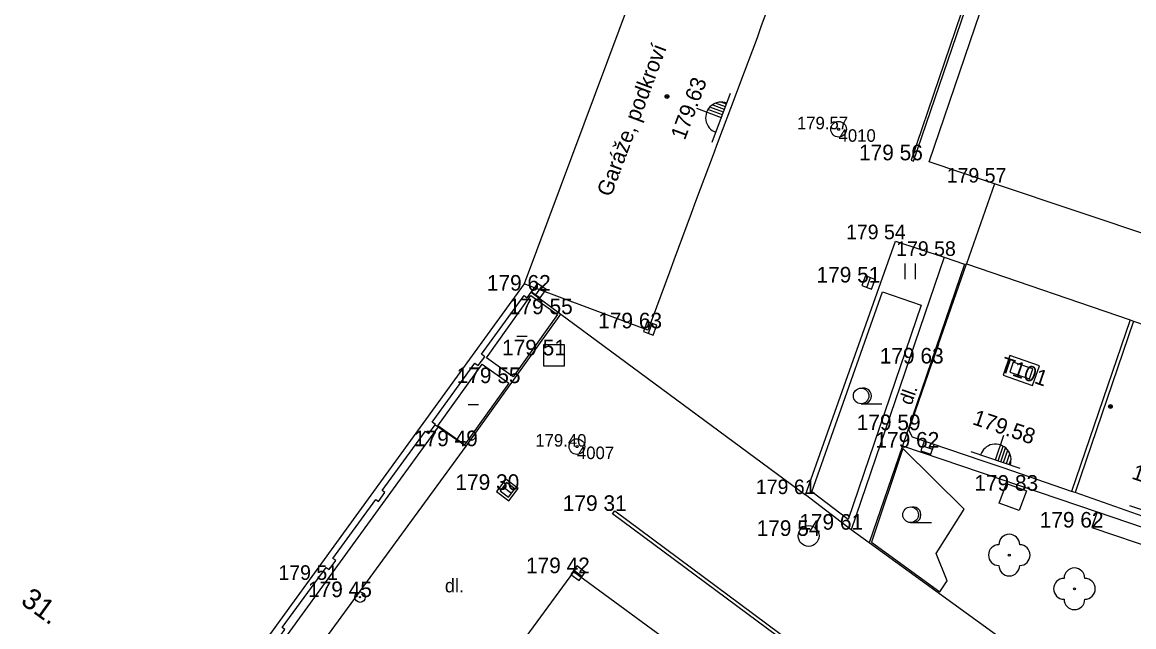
# Model space of a CAD drawing. Extents: x -537755 to -537431, y -1180722 to -1180510.
# Drawn here: x -537558.4 to -537505, y -1180613 to -1180583.9 of the extents above; entities that cross this region are included whole.
import ezdxf

# ---------------------------------------------------------------- set-up
doc = ezdxf.new("R2010")
doc.units = 0
for name, color, linetype in [('Vrstva 1', 7, 'Continuous'), ('Vrstva 10', 7, 'Continuous'), ('Vrstva 11', 7, 'Continuous'), ('Vrstva 21', 7, 'Continuous'), ('Vrstva 22', 7, 'Continuous'), ('Vrstva 23', 7, 'Continuous'), ('Vrstva 24', 7, 'Continuous'), ('Vrstva 25', 7, 'Continuous'), ('Vrstva 26', 7, 'Continuous'), ('Vrstva 27', 7, 'Continuous'), ('Vrstva 3', 7, 'Continuous'), ('Vrstva 36', 7, 'Continuous'), ('Vrstva 37', 7, 'Continuous'), ('Vrstva 39', 7, 'Continuous'), ('Vrstva 40', 7, 'Continuous'), ('Vrstva 41', 7, 'Continuous'), ('Vrstva 47', 7, 'Continuous'), ('Vrstva 5', 7, 'Continuous'), ('Vrstva 6', 7, 'Continuous'), ('Vrstva 7', 7, 'Continuous'), ('Vrstva 8', 7, 'Continuous')]:
    doc.layers.add(name, color=color, linetype=linetype)

msp = doc.modelspace()

# ---------------------------------------------------------------- linework, layer by layer
at = {"layer": 'Vrstva 1'}
for p, q in [((-537523.07, -1180584.66), (-537523.07, -1180584.66)), ((-537524.12, -1180587.47), (-537524.12, -1180587.47)), ((-537525.17, -1180590.29), (-537525.17, -1180590.29)), ((-537515.67, -1180590.55), (-537515.67, -1180590.55)), ((-537515.13, -1180590.55), (-537515.13, -1180590.55)), ((-537512.78, -1180591.38), (-537512.78, -1180591.38)), ((-537511.79, -1180591.73), (-537511.79, -1180591.73)), ((-537511.62, -1180591.62), (-537511.62, -1180591.62)), ((-537516.46, -1180594.34), (-537516.46, -1180594.34)), ((-537527.06, -1180595.35), (-537527.06, -1180595.35)), ((-537514.05, -1180595.14), (-537514.05, -1180595.14)), ((-537513.07, -1180595.43), (-537513.07, -1180595.43)), ((-537513.01, -1180595.53), (-537513.01, -1180595.53)), ((-537517.71, -1180596.42), (-537517.71, -1180596.42)), ((-537534.12, -1180597.12), (-537534.12, -1180597.12)), ((-537534.11, -1180597.15), (-537534.11, -1180597.15)), ((-537533.55, -1180596.81), (-537533.55, -1180596.81)), ((-537532.65, -1180597.96), (-537532.65, -1180597.96)), ((-537532.49, -1180597.94), (-537532.49, -1180597.94)), ((-537528.11, -1180598.17), (-537528.11, -1180598.17)), ((-537528.32, -1180598.7), (-537528.32, -1180598.7)), ((-537528.2, -1180598.62), (-537528.2, -1180598.62)), ((-537532.82, -1180599.92), (-537532.82, -1180599.92)), ((-537514.67, -1180600.31), (-537514.67, -1180600.31)), ((-537535, -1180601.25), (-537535, -1180601.25)), ((-537534.78, -1180600.95), (-537534.78, -1180600.95)), ((-537537.57, -1180602.14), (-537537.57, -1180602.14)), ((-537536.26, -1180603.2), (-537536.26, -1180603.2)), ((-537515.78, -1180603.51), (-537515.78, -1180603.51)), ((-537515.6, -1180603.84), (-537515.6, -1180603.84)), ((-537537.12, -1180604.21), (-537537.12, -1180604.21)), ((-537537.05, -1180604.28), (-537537.05, -1180604.28)), ((-537516.08, -1180604.26), (-537516.08, -1180604.26)), ((-537514.88, -1180604.35), (-537514.88, -1180604.35)), ((-537512.15, -1180605.02), (-537512.15, -1180605.02)), ((-537511.08, -1180606.07), (-537511.08, -1180606.07)), ((-537535.06, -1180606.38), (-537535.06, -1180606.38)), ((-537520.79, -1180606.58), (-537520.79, -1180606.58)), ((-537510.13, -1180606.42), (-537510.13, -1180606.42)), ((-537541.26, -1180606.94), (-537541.26, -1180606.94)), ((-537534.99, -1180606.9), (-537534.99, -1180606.9)), ((-537513.11, -1180607.3), (-537513.11, -1180607.3)), ((-537529.9, -1180607.39), (-537529.9, -1180607.39)), ((-537506.73, -1180607.43), (-537506.73, -1180607.43)), ((-537518.54, -1180608.29), (-537518.54, -1180608.29)), ((-537506.99, -1180608.19), (-537506.99, -1180608.19)), ((-537520.59, -1180608.59), (-537520.59, -1180608.59)), ((-537514.46, -1180609.44), (-537514.46, -1180609.44)), ((-537510.95, -1180609.51), (-537510.95, -1180609.51)), ((-537543.62, -1180610.2), (-537543.62, -1180610.2)), ((-537531.89, -1180610.31), (-537531.89, -1180610.31)), ((-537531.67, -1180610.38), (-537531.67, -1180610.38)), ((-537543.73, -1180610.7), (-537543.73, -1180610.7)), ((-537513.93, -1180610.74), (-537513.93, -1180610.74)), ((-537542.14, -1180611.53), (-537542.14, -1180611.53)), ((-537507.82, -1180611.13), (-537507.82, -1180611.13))]:
    msp.add_line(p, q, dxfattribs=at)
at = {"layer": 'Vrstva 10'}
for p, q in [((-537491.645, -1180598.392), (-537511.66, -1180591.68)), ((-537520.733, -1180606.623), (-537516.42, -1180594.43)), ((-537537.05, -1180604.28), (-537532.49, -1180597.94)), ((-537544.365, -1180614.287), (-537537.05, -1180604.28)), ((-537518.54, -1180608.29), (-537520.733, -1180606.623)), ((-537517.675, -1180608.917), (-537518.54, -1180608.29)), ((-537502.79, -1180619.71), (-537517.675, -1180608.917))]:
    msp.add_line(p, q, dxfattribs=at)
msp.add_lwpolyline([(-537516.42, -1180594.43), (-537514.076, -1180595.208), (-537513.104, -1180595.531), (-537513.01, -1180595.53)], dxfattribs=at)
at = {"layer": 'Vrstva 11'}
for p, q in [((-537510.498, -1180575.39), (-537515.67, -1180590.55)), ((-537515.547, -1180590.592), (-537510.376, -1180575.435)), ((-537515.67, -1180590.55), (-537515.547, -1180590.592)), ((-537514.076, -1180595.208), (-537518.54, -1180608.29)), ((-537513.104, -1180595.531), (-537516.08, -1180604.26)), ((-537533.919, -1180596.884), (-537532.49, -1180597.94)), ((-537532.49, -1180597.94), (-537520.733, -1180606.623)), ((-537538.392, -1180603.352), (-537545.644, -1180613.334)), ((-537516.08, -1180604.26), (-537517.675, -1180608.917)), ((-537516.08, -1180604.26), (-537506.73, -1180607.43)), ((-537530.007, -1180607.535), (-537529.9, -1180607.39)), ((-537515.91, -1180617.97), (-537530.007, -1180607.535)), ((-537529.9, -1180607.39), (-537515.81, -1180617.84)), ((-537506.73, -1180607.43), (-537506.99, -1180608.19)), ((-537506.73, -1180607.43), (-537499.88, -1180609.77)), ((-537506.99, -1180608.19), (-537493.67, -1180612.7))]:
    msp.add_line(p, q, dxfattribs=at)
for points in [[(-537538.525, -1180603.26), (-537538.392, -1180603.352), (-537537.05, -1180604.28)], [(-537535.58, -1180606.45), (-537534.99, -1180606.9), (-537534.54, -1180606.31), (-537535.13, -1180605.86), (-537535.58, -1180606.45)], [(-537511.08, -1180606.07), (-537510.13, -1180606.42), (-537510.48, -1180607.37), (-537511.43, -1180607.02), (-537511.08, -1180606.07)]]:
    msp.add_lwpolyline(points, dxfattribs=at)
at = {"layer": 'Vrstva 21'}
for p, q in [((-537520.434, -1180606.474), (-537517.038, -1180596.873)), ((-537517.038, -1180596.873), (-537515.176, -1180597.509)), ((-537515.176, -1180597.509), (-537518.69, -1180607.8)), ((-537518.69, -1180607.8), (-537520.434, -1180606.474)), ((-537513.93, -1180610.74), (-537514.46, -1180609.44))]:
    msp.add_line(p, q, dxfattribs=at)
for points in [[(-537516.059, -1180604.392), (-537517.563, -1180608.893), (-537514.285, -1180611.282), (-537513.93, -1180610.74)], [(-537514.46, -1180609.44), (-537513.11, -1180607.3), (-537516.059, -1180604.392)]]:
    msp.add_lwpolyline(points, dxfattribs=at)
for centre, radius in [((-537519.15, -1180589.06), 0.375), ((-537519.15, -1180589.06), 0.05), ((-537531.72, -1180604.3), 0.375), ((-537531.72, -1180604.3), 0.05)]:
    msp.add_circle(centre, radius, dxfattribs=at)
at = {"layer": 'Vrstva 22'}
for centre in [(-537510.95, -1180609.51), (-537507.82, -1180611.13)]:
    msp.add_circle(centre, 0.05, dxfattribs=at)
for centre, start, end in [((-537510.95, -1180609.01), 0, 180), ((-537511.45, -1180609.51), 90, 270), ((-537510.45, -1180609.51), 270, 90), ((-537510.95, -1180610.01), 180, 0), ((-537507.82, -1180610.63), 0, 180), ((-537508.32, -1180611.13), 90, 270), ((-537507.32, -1180611.13), 270, 90), ((-537507.82, -1180611.63), 180, 0)]:
    msp.add_arc(centre, 0.5, start, end, dxfattribs=at)
at = {"layer": 'Vrstva 24'}
for points in [[(-537509.504, -1180600.416), (-537510.923, -1180599.93), (-537511.246, -1180600.876), (-537509.827, -1180601.362)], [(-537509.821, -1180600.571), (-537510.767, -1180600.248), (-537510.929, -1180600.721), (-537509.983, -1180601.044)]]:
    msp.add_lwpolyline(points, close=True, dxfattribs=at)
at = {"layer": 'Vrstva 25'}
for radius in [0.25, 0.0303]:
    msp.add_circle((-537542.14, -1180611.53), radius, dxfattribs=at)
at = {"layer": 'Vrstva 26'}
msp.add_lwpolyline([(-537533.32, -1180600.42), (-537532.32, -1180600.42), (-537532.32, -1180599.42), (-537533.32, -1180599.42)], close=True, dxfattribs=at)
at = {"layer": 'Vrstva 27'}
for p, q in [((-537533.695, -1180597.014), (-537533.405, -1180596.606)), ((-537517.797, -1180596.654), (-537517.623, -1180596.186)), ((-537528.287, -1180598.854), (-537528.113, -1180598.386)), ((-537515.117, -1180604.269), (-537514.643, -1180604.431)), ((-537535.259, -1180606.228), (-537534.861, -1180606.532)), ((-537531.872, -1180610.233), (-537531.468, -1180610.527))]:
    msp.add_line(p, q, dxfattribs=at)
for points in [[(-537517.563, -1180596.742), (-537517.388, -1180596.273), (-537517.857, -1180596.098), (-537518.032, -1180596.567)], [(-537533.491, -1180597.159), (-537533.201, -1180596.751), (-537533.609, -1180596.461), (-537533.899, -1180596.869)], [(-537528.053, -1180598.942), (-537527.878, -1180598.473), (-537528.347, -1180598.298), (-537528.522, -1180598.767)], [(-537515.197, -1180604.506), (-537514.724, -1180604.667), (-537514.563, -1180604.194), (-537515.036, -1180604.033)], [(-537535.41, -1180606.427), (-537535.013, -1180606.73), (-537534.71, -1180606.333), (-537535.107, -1180606.03)], [(-537532.019, -1180610.435), (-537531.615, -1180610.729), (-537531.321, -1180610.325), (-537531.725, -1180610.031)]]:
    msp.add_lwpolyline(points, close=True, dxfattribs=at)
msp.add_circle((-537520.59, -1180608.59), 0.5, dxfattribs=at)
at = {"layer": 'Vrstva 36'}
for p, q in [((-537515.954, -1180596.258), (-537515.954, -1180595.508)), ((-537515.454, -1180596.258), (-537515.454, -1180595.508)), ((-537518.067, -1180602.242), (-537517.067, -1180602.242)), ((-537515.693, -1180607.95), (-537514.693, -1180607.95))]:
    msp.add_line(p, q, dxfattribs=at)
for centre in [(-537518.067, -1180601.867), (-537515.693, -1180607.575)]:
    msp.add_circle(centre, 0.375, dxfattribs=at)
for centre in [(-537517.942, -1180601.867), (-537515.568, -1180607.575)]:
    msp.add_arc(centre, 0.375, 260.4059, 99.5941, dxfattribs=at)
at = {"layer": 'Vrstva 37'}
for p, q in [((-537525.219, -1180589.675), (-537524.343, -1180587.333)), ((-537524.781, -1180588.504), (-537525.959, -1180588.064)), ((-537524.683, -1180588.242), (-537525.342, -1180587.995)), ((-537524.634, -1180588.111), (-537525.224, -1180587.89)), ((-537524.585, -1180587.979), (-537525.06, -1180587.802)), ((-537524.536, -1180587.848), (-537524.796, -1180587.751)), ((-537524.732, -1180588.373), (-537525.43, -1180588.112)), ((-537511.619, -1180604.936), (-537511.213, -1180603.745)), ((-537512.802, -1180604.533), (-537510.436, -1180605.339)), ((-537511.486, -1180604.981), (-537511.246, -1180604.276)), ((-537511.354, -1180605.026), (-537511.127, -1180604.36)), ((-537511.221, -1180605.071), (-537511.018, -1180604.475)), ((-537511.089, -1180605.117), (-537510.925, -1180604.637)), ((-537510.956, -1180605.162), (-537510.867, -1180604.899)), ((-537502.787, -1180607.951), (-537505.153, -1180607.145))]:
    msp.add_line(p, q, dxfattribs=at)
for centre, start, end in [((-537524.789, -1180588.501), 68.8879, 250.134), ((-537511.616, -1180604.928), 340.5581, 161.8041)]:
    msp.add_arc(centre, 0.75, start, end, dxfattribs=at)
at = {"layer": 'Vrstva 39'}
for p, q in [((-537534.607, -1180598.998), (-537534.107, -1180598.998)), ((-537536.949, -1180602.273), (-537536.449, -1180602.273))]:
    msp.add_line(p, q, dxfattribs=at)
for centre, radius in [((-537527.395, -1180587.486), 0.09), ((-537527.395, -1180587.486), 0.0398), ((-537506.089, -1180602.372), 0.09), ((-537506.089, -1180602.372), 0.0398)]:
    msp.add_circle(centre, radius, dxfattribs=at)
at = {"layer": 'Vrstva 5'}
for p, q in [((-537526.673, -1180576.192), (-537534.25, -1180596.49)), ((-537522.865, -1180584.086), (-537523.07, -1180584.66)), ((-537523.917, -1180586.905), (-537524.12, -1180587.47)), ((-537524.966, -1180589.716), (-537525.17, -1180590.29)), ((-537526.019, -1180592.535), (-537526.229, -1180593.098)), ((-537527.06, -1180595.35), (-537527.281, -1180595.918)), ((-537514.345, -1180599.375), (-537513.01, -1180595.53)), ((-537513.01, -1180595.53), (-537505.147, -1180598.219)), ((-537533.766, -1180596.67), (-537534.25, -1180596.49)), ((-537536.064, -1180600.035), (-537533.934, -1180597.045)), ((-537533.934, -1180597.045), (-537532.65, -1180597.96)), ((-537528.32, -1180598.7), (-537533.766, -1180596.67)), ((-537532.65, -1180597.96), (-537534.78, -1180600.95)), ((-537528.11, -1180598.17), (-537528.32, -1180598.7)), ((-537505.147, -1180598.219), (-537507.961, -1180606.449)), ((-537505.147, -1180598.219), (-537504.976, -1180598.278)), ((-537504.976, -1180598.278), (-537507.791, -1180606.507)), ((-537504.976, -1180598.278), (-537497.538, -1180600.822)), ((-537515.78, -1180603.51), (-537514.345, -1180599.375)), ((-537538.397, -1180603.295), (-537536.277, -1180600.335)), ((-537536.277, -1180600.335), (-537535, -1180601.25)), ((-537534.78, -1180600.95), (-537536.064, -1180600.035)), ((-537535, -1180601.25), (-537537.12, -1180604.21)), ((-537537.12, -1180604.21), (-537538.397, -1180603.295)), ((-537515.6, -1180603.84), (-537515.78, -1180603.51)), ((-537512.15, -1180605.02), (-537515.6, -1180603.84)), ((-537507.961, -1180606.449), (-537511.25, -1180605.325)), ((-537507.791, -1180606.507), (-537507.961, -1180606.449)), ((-537504.51, -1180607.66), (-537507.791, -1180606.507)), ((-537531.89, -1180610.31), (-537538.253, -1180619.002)), ((-537523.2, -1180616.68), (-537531.89, -1180610.31))]:
    msp.add_line(p, q, dxfattribs=at)
at = {"layer": 'Vrstva 6'}
for p, q in [((-537522.02, -1180581.84), (-537522.865, -1180584.086)), ((-537523.07, -1180584.66), (-537523.917, -1180586.905)), ((-537524.12, -1180587.47), (-537524.966, -1180589.716)), ((-537525.17, -1180590.29), (-537526.019, -1180592.535)), ((-537526.229, -1180593.098), (-537527.06, -1180595.35)), ((-537527.281, -1180595.918), (-537528.11, -1180598.17)), ((-537514.345, -1180599.375), (-537514.67, -1180600.31)), ((-537511.25, -1180605.325), (-537512.15, -1180605.02))]:
    msp.add_line(p, q, dxfattribs=at)
at = {"layer": 'Vrstva 7'}
for p, q in [((-537514.8, -1180590.62), (-537505.614, -1180563.66)), ((-537511.66, -1180591.68), (-537514.8, -1180590.62)), ((-537534.25, -1180596.49), (-537553.389, -1180622.832))]:
    msp.add_line(p, q, dxfattribs=at)
for points in [[(-537538.991, -1180603.553), (-537538.83, -1180603.67), (-537538.525, -1180603.26), (-537538.513, -1180603.244), (-537538.679, -1180603.123), (-537536.621, -1180600.3), (-537536.47, -1180600.41), (-537536.153, -1180599.984), (-537536.312, -1180599.868), (-537534.25, -1180597.048), (-537534.11, -1180597.15), (-537533.919, -1180596.884), (-537533.766, -1180596.67)], [(-537543.767, -1180610.102), (-537543.62, -1180610.2), (-537543.303, -1180609.774), (-537543.455, -1180609.673), (-537541.389, -1180606.845), (-537541.26, -1180606.94), (-537540.951, -1180606.509), (-537541.08, -1180606.415), (-537538.991, -1180603.553)], [(-537546.15, -1180613.37), (-537546.03, -1180613.46), (-537545.833, -1180613.193), (-537545.75, -1180613.08), (-537545.88, -1180612.99), (-537543.767, -1180610.102)]]:
    msp.add_lwpolyline(points, dxfattribs=at)
at = {"layer": 'Vrstva 8'}
msp.add_line((-537511.66, -1180591.68), (-537513.01, -1180595.53), dxfattribs=at)

# ---------------------------------------------------------------- texts
at = {"layer": 'Vrstva 22'}
for s, p in [('179.57 ', (-537521.15, -1180589.06)), ('179.40 ', (-537533.72, -1180604.3))]:
    msp.add_text(s, height=0.6, dxfattribs=at).set_placement(p)
at = {"layer": 'Vrstva 23'}
for s, p in [('4010', (-537519.15, -1180589.66)), ('4007', (-537531.72, -1180604.9))]:
    msp.add_text(s, height=0.6, dxfattribs=at).set_placement(p)
at = {"layer": 'Vrstva 3'}
for s, height, p in [('179 56 ', 0.75, (-537518.17, -1180590.55)), ('179 57 ', 0.7, (-537513.953, -1180591.62)), ('179 54 ', 0.7, (-537518.793, -1180594.34)), ('179 58 ', 0.7, (-537516.383, -1180595.14)), ('179 62 ', 0.75, (-537536.05, -1180596.81)), ('179 51 ', 0.75, (-537520.21, -1180596.42)), ('179 55 ', 0.75, (-537534.99, -1180597.94)), ('179 63 ', 0.75, (-537530.7, -1180598.62)), ('179 51 ', 0.75, (-537535.32, -1180599.92)), ('179 63 ', 0.75, (-537517.17, -1180600.31)), ('179 55 ', 0.75, (-537537.5, -1180601.25)), ('179 59 ', 0.75, (-537518.28, -1180603.51)), ('179 49 ', 0.75, (-537539.55, -1180604.28)), ('179 62 ', 0.75, (-537517.38, -1180604.35)), ('179 30 ', 0.75, (-537537.56, -1180606.38)), ('179 83 ', 0.75, (-537512.63, -1180606.42)), ('179 61 ', 0.7, (-537523.123, -1180606.58)), ('179 31 ', 0.75, (-537532.4, -1180607.39)), ('179 54 ', 0.75, (-537523.09, -1180608.59)), ('179 61 ', 0.75, (-537521.04, -1180608.29)), ('179 62 ', 0.75, (-537509.49, -1180608.19)), ('179 42 ', 0.75, (-537534.17, -1180610.38)), ('179 51 ', 0.7, (-537546.063, -1180610.7)), ('179 45 ', 0.75, (-537544.64, -1180611.53))]:
    msp.add_text(s, height=height, dxfattribs=at).set_placement(p)
at = {"layer": 'Vrstva 37'}
for s, rotation, p in [('179.63', 69.5307, (-537526.539, -1180589.617)), ('179.58', 341.1188, (-537512.763, -1180603.214)), ('179.58', 341.1188, (-537505.114, -1180605.826))]:
    msp.add_text(s, height=0.75, rotation=rotation, dxfattribs=at).set_placement(p)
at = {"layer": 'Vrstva 40'}
msp.add_text('dl.', height=0.65, rotation=70.7774, dxfattribs=at).set_placement((-537515.649, -1180602.347))
msp.add_text('dl.', height=0.65, dxfattribs=at).set_placement((-537538.064, -1180611.301))
at = {"layer": 'Vrstva 41'}
for s, rotation, p in [('Garáže, podkroví', 69.5305, (-537530.087, -1180592.342)), ('T101', 341.1188, (-537511.428, -1180600.68))]:
    msp.add_text(s, height=0.75, rotation=rotation, dxfattribs=at).set_placement(p)
at = {"layer": 'Vrstva 47'}
msp.add_text('31.', height=1, rotation=324.0548, dxfattribs=at).set_placement((-537558.497, -1180611.816))

doc.saveas('drawing.dxf')
